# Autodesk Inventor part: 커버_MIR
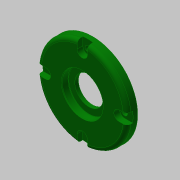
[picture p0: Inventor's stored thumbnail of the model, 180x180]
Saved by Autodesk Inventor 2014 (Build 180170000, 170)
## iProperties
Created: 2020-05
Part Number: 커버_MIR
Material: 알루미늄 6061
Document SubType Name: Modeling
Designer: kh
Density: 2.71 g/cm^3
Appearance: Aluminum - Flat
Author: mduedu
d0: 70.000 mm
d2: 47.000 mm
d3: 4.000 mm
d4: 12.000 mm
d8: 22.000 mm
d10: 32.000 mm
d11: 5.200 mm
d17: 40.000 mm
d22: 4.000 mm
d24: 3.000 mm
d25: 3.000 mm
d26: 0.300 mm
d27: 0.500 mm
d29: 30.00 deg
d30: 1.000 mm
d33: 57.000 mm
d34: 8.000 mm
d35: 10.000 mm
d36: 4.400 mm
d37: 0.00 deg
d38: 4.500 mm
d45: 4.000 ul
d46: 360.00 deg
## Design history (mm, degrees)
derived "커버.ipt"
  sketch "스케치1"
    geometry: L1 (0, 0)-(-8, 0) reference; L2 (-8, 0)-(-8, 35) reference; L3 (-8, 35)-(0, 35) reference; L4 (0, 35)-(0, 0) reference; L5 (-8, 0)-(-12, 0) reference; L6 (-12, 0)-(-12, 23.5) reference; L7 (-12, 23.5)-(-8, 23.5) reference; L8 (-8, 23.5)-(-8, 0) reference
  sketch "스케치2"
    geometry: L1 (4, 28.5)-(-4, 28.5) reference; L2 (-4, 28.5)-(-4, 38.5) reference; L3 (-4, 38.5)-(4, 38.5) reference; L4 (4, 38.5)-(4, 28.5) reference; 4 further points
    constraints: 2 horizontal alignment, 1 vertical alignment
  sketch "스케치3"
    geometry: A1 r 4 centre (0, 28.5) between (-4, 28.5) and (4, 28.5) reference; 2 further points
feature "솔리드1::커버.ipt"
tag "TaggingFeature1"
body "Solid1"
other parameters: "d0" = 10, "d2" = 47, "d3" = 4, "d4" = 12, "d8" = 22, "d10" = 32, "d11" = 5.2, "d17" = 40, "d22" = 4, "d24" = 3, "d25" = 3, "d26" = 0.3, "d27" = 0.5, "d29" = 30 deg, "d30" = 1, "d33" = 57, "d34" = 8, "d35" = 10, "d36" = 4.4, "d37" = 0 deg, "d38" = 4.5, "d45" = 4, "d46" = 360 deg
